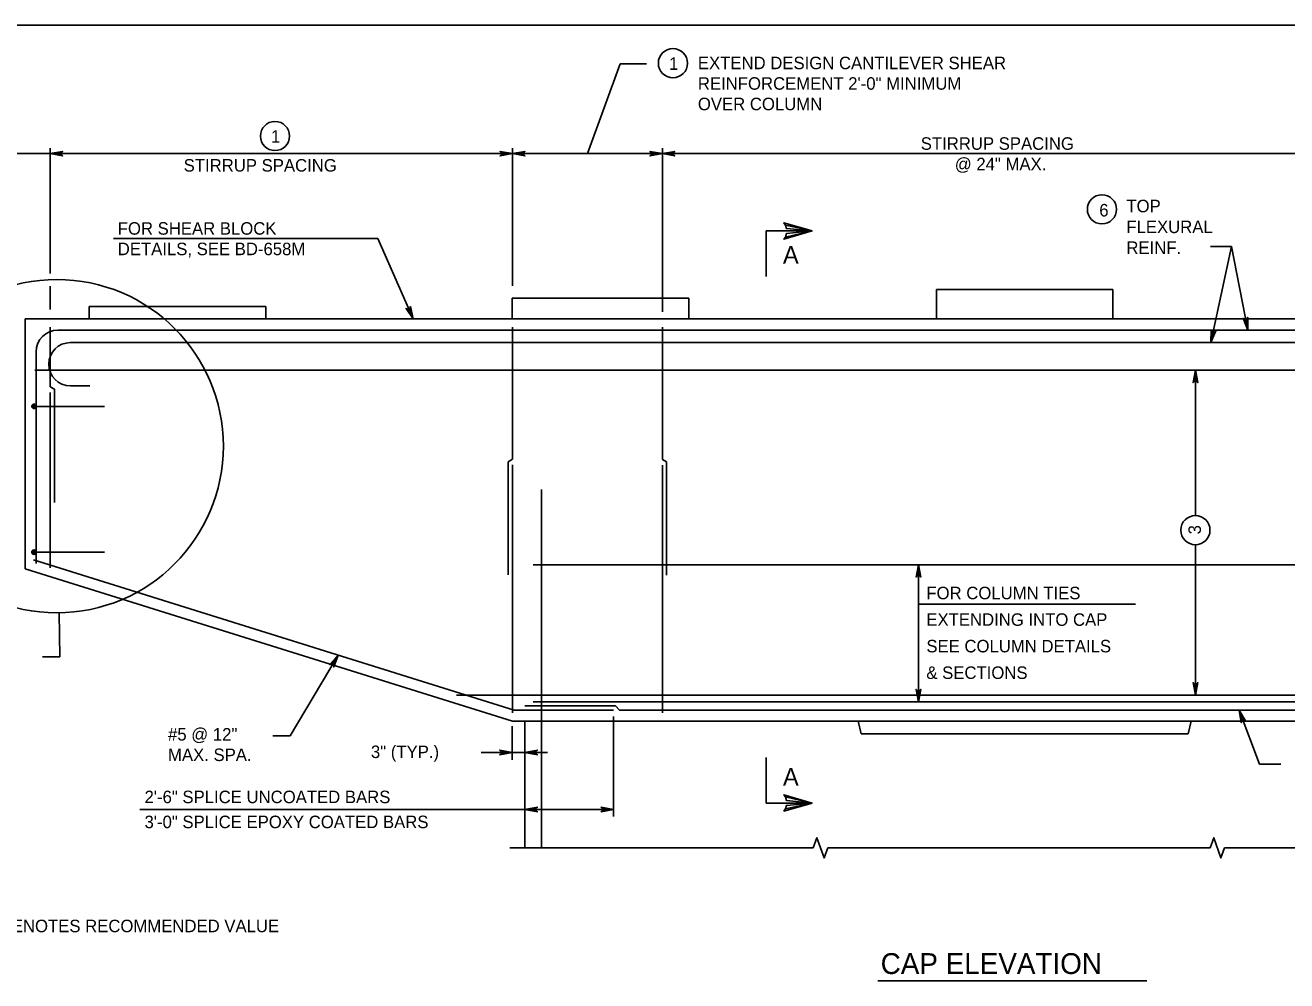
# Model space of a CAD drawing. Extents: x 646165 to 651486, y 296916 to 299292.
# Drawn here: x 649267.7 to 649570.7, y 298453.9 to 298683.3 of the extents above; entities that cross this region are included whole.
import ezdxf

# ---------------------------------------------------------------- set-up
doc = ezdxf.new("R2010")
doc.units = 0
for name, color, linetype in [('1', 7, 'Continuous'), ('2', 7, 'Continuous'), ('51', 7, 'Continuous'), ('52', 7, 'Continuous'), ('53', 7, 'Continuous'), ('54', 7, 'Continuous')]:
    doc.layers.add(name, color=color, linetype=linetype)

msp = doc.modelspace()

# ---------------------------------------------------------------- linework, layer by layer
at = {"layer": '1'}
for p, q in [((649445.63, 298633.87), (649445.63, 298622.94)), ((649456.7, 298633.87), (649445.63, 298633.87)), ((649445.63, 298496.53), (649445.63, 298507.45)), ((649456.7, 298496.53), (649445.63, 298496.53))]:
    msp.add_line(p, q, dxfattribs=at)
for points in [[(649450.28, 298632.4), (649450.52, 298633.24), (649456.7, 298633.87), (649450.28, 298632.4), (649449.95, 298631.88), (649456.7, 298633.87), (649450.52, 298634.43), (649450.3, 298635.26), (649456.7, 298633.87), (649449.95, 298635.82), (649450.3, 298635.26)], [(649450.28, 298498), (649450.52, 298497.15), (649456.7, 298496.53), (649450.28, 298498), (649449.95, 298498.52), (649456.7, 298496.53), (649450.52, 298495.97), (649450.3, 298495.14), (649456.7, 298496.53), (649449.95, 298494.58), (649450.3, 298495.14)]]:
    msp.add_lwpolyline(points, dxfattribs=at)
at = {"layer": '2'}
msp.add_line((648988.59, 298683.25), (649774.59, 298683.25), dxfattribs=at)
at = {"layer": '51'}
for p, q in [((649384.7, 298617.77), (649384.7, 298612.75)), ((649384.7, 298617.77), (649427.1, 298617.77)), ((649427.1, 298617.77), (649427.1, 298612.75)), ((649486.54, 298619.81), (649486.54, 298612.75)), ((649486.54, 298619.81), (649528.94, 298619.81)), ((649528.94, 298619.81), (649528.94, 298612.75)), ((649283.1, 298615.75), (649283.1, 298612.75)), ((649283.1, 298615.75), (649325.5, 298615.75)), ((649325.5, 298615.75), (649325.5, 298612.75)), ((649267.74, 298612.75), (649747.74, 298612.75)), ((649267.74, 298612.75), (649267.74, 298552.75)), ((649384.74, 298516.15), (649267.74, 298552.75)), ((649384.74, 298516.15), (649630.74, 298516.15)), ((649387.74, 298516.15), (649387.74, 298485.78)), ((649467.74, 298516.15), (649468.51, 298513.15)), ((649547.74, 298516.15), (649546.97, 298513.15)), ((649468.51, 298513.15), (649546.97, 298513.15))]:
    msp.add_line(p, q, dxfattribs=at)
at = {"layer": '52'}
for p, q in [((649402.74, 298652.42), (649410.58, 298673.95)), ((649416.91, 298673.95), (649410.58, 298673.95)), ((649273.74, 298653.75), (649273.74, 298623.63)), ((649384.74, 298653.75), (649384.74, 298620.72)), ((649420.74, 298653.75), (649420.74, 298614.41)), ((649261.37, 298652.42), (649384.74, 298652.42)), ((649384.74, 298652.42), (649630.74, 298652.42)), ((649288.97, 298632.05), (649352.43, 298632.05)), ((649360.92, 298612.75), (649352.43, 298632.05)), ((649557.45, 298630.13), (649552.34, 298630.13)), ((649557.45, 298630.13), (649552.45, 298607.07)), ((649557.45, 298630.13), (649561.33, 298610.07)), ((649273.74, 298620.65), (649273.74, 298614.98)), ((649548.74, 298600.45), (649548.74, 298565.54)), ((649548.74, 298558.54), (649548.74, 298522.45)), ((649482.24, 298553.74), (649482.24, 298520.83)), ((649275.92, 298542.21), (649276.09, 298531.64)), ((649482.24, 298544.24), (649534.34, 298544.24)), ((649271.89, 298531.64), (649276.09, 298531.64)), ((649342.87, 298532.05), (649331.36, 298512.67)), ((649409.02, 298517.29), (649409.02, 298493.26)), ((649559.22, 298518.83), (649564.12, 298505.83)), ((649384.69, 298514.99), (649384.69, 298506.93)), ((649327.16, 298512.67), (649331.36, 298512.67)), ((649377.22, 298508.68), (649393.15, 298508.68)), ((649569.23, 298505.83), (649564.12, 298505.83)), ((649295.29, 298494.98), (649409.02, 298494.98)), ((649384.1, 298485.78), (649456.96, 298485.78)), ((649460.46, 298485.78), (649552.25, 298485.78)), ((649555.75, 298485.78), (649631.35, 298485.78))]:
    msp.add_line(p, q, dxfattribs=at)
for points in [[(649273.74, 298652.42), (649276.72, 298652.98), (649276.61, 298652.9), (649276.49, 298652.82), (649276.43, 298652.72), (649276.38, 298652.62), (649276.36, 298652.52), (649276.34, 298652.42), (649276.36, 298652.32), (649276.38, 298652.22), (649276.43, 298652.12), (649276.49, 298652.02), (649276.61, 298651.95), (649276.72, 298651.87), (649273.74, 298652.42), (649276.61, 298651.95), (649276.49, 298652.02), (649273.74, 298652.42), (649276.43, 298652.12), (649276.38, 298652.22), (649273.74, 298652.42), (649276.36, 298652.32), (649276.34, 298652.42), (649273.74, 298652.42), (649276.36, 298652.52), (649276.38, 298652.62), (649273.74, 298652.42), (649276.43, 298652.72), (649276.49, 298652.82), (649273.74, 298652.42), (649276.61, 298652.9)], [(649384.74, 298652.42), (649381.76, 298651.87), (649381.87, 298651.95), (649381.99, 298652.02), (649382.05, 298652.12), (649382.11, 298652.22), (649382.12, 298652.32), (649382.14, 298652.42), (649382.12, 298652.52), (649382.11, 298652.62), (649382.05, 298652.72), (649381.99, 298652.82), (649381.87, 298652.9), (649381.76, 298652.98), (649384.74, 298652.42), (649381.87, 298652.9), (649381.99, 298652.82), (649384.74, 298652.42), (649382.05, 298652.72), (649382.11, 298652.62), (649384.74, 298652.42), (649382.12, 298652.52), (649382.14, 298652.42), (649384.74, 298652.42), (649382.12, 298652.32), (649382.11, 298652.22), (649384.74, 298652.42), (649382.05, 298652.12), (649381.99, 298652.02), (649384.74, 298652.42), (649381.87, 298651.95)], [(649384.74, 298652.42), (649387.72, 298651.87), (649387.61, 298651.95), (649387.49, 298652.02), (649387.43, 298652.12), (649387.38, 298652.22), (649387.36, 298652.32), (649387.34, 298652.42), (649387.36, 298652.52), (649387.38, 298652.62), (649387.43, 298652.72), (649387.49, 298652.82), (649387.61, 298652.9), (649387.72, 298652.98), (649384.74, 298652.42), (649387.61, 298652.9), (649387.49, 298652.82), (649384.74, 298652.42), (649387.43, 298652.72), (649387.38, 298652.62), (649384.74, 298652.42), (649387.36, 298652.52), (649387.34, 298652.42), (649384.74, 298652.42), (649387.36, 298652.32), (649387.38, 298652.22), (649384.74, 298652.42), (649387.43, 298652.12), (649387.49, 298652.02), (649384.74, 298652.42), (649387.61, 298651.95)], [(649420.74, 298652.42), (649417.76, 298651.87), (649417.87, 298651.95), (649417.99, 298652.02), (649418.05, 298652.12), (649418.11, 298652.22), (649418.12, 298652.32), (649418.14, 298652.42), (649418.12, 298652.52), (649418.11, 298652.62), (649418.05, 298652.72), (649417.99, 298652.82), (649417.87, 298652.9), (649417.76, 298652.98), (649420.74, 298652.42), (649417.87, 298652.9), (649417.99, 298652.82), (649420.74, 298652.42), (649418.05, 298652.72), (649418.11, 298652.62), (649420.74, 298652.42), (649418.12, 298652.52), (649418.14, 298652.42), (649420.74, 298652.42), (649418.12, 298652.32), (649418.11, 298652.22), (649420.74, 298652.42), (649418.05, 298652.12), (649417.99, 298652.02), (649420.74, 298652.42), (649417.87, 298651.95)], [(649420.74, 298652.42), (649423.72, 298651.87), (649423.61, 298651.95), (649423.49, 298652.02), (649423.43, 298652.12), (649423.38, 298652.22), (649423.36, 298652.32), (649423.34, 298652.42), (649423.36, 298652.52), (649423.38, 298652.62), (649423.43, 298652.72), (649423.49, 298652.82), (649423.61, 298652.9), (649423.72, 298652.98), (649420.74, 298652.42), (649423.61, 298652.9), (649423.49, 298652.82), (649420.74, 298652.42), (649423.43, 298652.72), (649423.38, 298652.62), (649420.74, 298652.42), (649423.36, 298652.52), (649423.34, 298652.42), (649420.74, 298652.42), (649423.36, 298652.32), (649423.38, 298652.22), (649420.74, 298652.42), (649423.43, 298652.12), (649423.49, 298652.02), (649420.74, 298652.42), (649423.61, 298651.95)], [(649360.92, 298612.75), (649359.2, 298615.25), (649359.32, 298615.18), (649359.44, 298615.1), (649359.56, 298615.09), (649359.67, 298615.08), (649359.77, 298615.1), (649359.87, 298615.13), (649359.95, 298615.18), (649360.04, 298615.24), (649360.11, 298615.33), (649360.17, 298615.43), (649360.2, 298615.56), (649360.23, 298615.7), (649360.92, 298612.75), (649360.2, 298615.56), (649360.17, 298615.43), (649360.92, 298612.75), (649360.11, 298615.33), (649360.04, 298615.24), (649360.92, 298612.75), (649359.95, 298615.18), (649359.87, 298615.13), (649360.92, 298612.75), (649359.77, 298615.1), (649359.67, 298615.08), (649360.92, 298612.75), (649359.56, 298615.09), (649359.44, 298615.1), (649360.92, 298612.75), (649359.32, 298615.18)], [(649561.33, 298610.07), (649560.21, 298612.89), (649560.31, 298612.79), (649560.41, 298612.69), (649560.52, 298612.65), (649560.63, 298612.61), (649560.73, 298612.62), (649560.83, 298612.62), (649560.93, 298612.65), (649561.02, 298612.69), (649561.11, 298612.77), (649561.2, 298612.84), (649561.25, 298612.97), (649561.31, 298613.1), (649561.33, 298610.07), (649561.25, 298612.97), (649561.2, 298612.84), (649561.33, 298610.07), (649561.11, 298612.77), (649561.02, 298612.69), (649561.33, 298610.07), (649560.93, 298612.65), (649560.83, 298612.62), (649561.33, 298610.07), (649560.73, 298612.62), (649560.63, 298612.61), (649561.33, 298610.07), (649560.52, 298612.65), (649560.41, 298612.69), (649561.33, 298610.07), (649560.31, 298612.79)], [(649552.45, 298607.07), (649552.54, 298610.1), (649552.59, 298609.97), (649552.65, 298609.84), (649552.73, 298609.76), (649552.82, 298609.68), (649552.91, 298609.64), (649553, 298609.61), (649553.11, 298609.6), (649553.21, 298609.6), (649553.32, 298609.63), (649553.43, 298609.67), (649553.53, 298609.77), (649553.63, 298609.86), (649552.45, 298607.07), (649553.53, 298609.77), (649553.43, 298609.67), (649552.45, 298607.07), (649553.32, 298609.63), (649553.21, 298609.6), (649552.45, 298607.07), (649553.11, 298609.6), (649553, 298609.61), (649552.45, 298607.07), (649552.91, 298609.64), (649552.82, 298609.68), (649552.45, 298607.07), (649552.73, 298609.76), (649552.65, 298609.84), (649552.45, 298607.07), (649552.59, 298609.97)], [(649548.74, 298600.45), (649549.3, 298597.46), (649549.22, 298597.58), (649549.14, 298597.69), (649549.04, 298597.75), (649548.94, 298597.81), (649548.84, 298597.83), (649548.74, 298597.85), (649548.64, 298597.83), (649548.54, 298597.81), (649548.44, 298597.75), (649548.34, 298597.69), (649548.26, 298597.58), (649548.18, 298597.46), (649548.74, 298600.45), (649548.26, 298597.58), (649548.34, 298597.69), (649548.74, 298600.45), (649548.44, 298597.75), (649548.54, 298597.81), (649548.74, 298600.45), (649548.64, 298597.83), (649548.74, 298597.85), (649548.74, 298600.45), (649548.84, 298597.83), (649548.94, 298597.81), (649548.74, 298600.45), (649549.04, 298597.75), (649549.14, 298597.69), (649548.74, 298600.45), (649549.22, 298597.58)], [(649482.24, 298553.74), (649482.8, 298550.76), (649482.72, 298550.87), (649482.64, 298550.99), (649482.54, 298551.05), (649482.44, 298551.11), (649482.34, 298551.12), (649482.24, 298551.14), (649482.14, 298551.12), (649482.04, 298551.11), (649481.94, 298551.05), (649481.84, 298550.99), (649481.76, 298550.87), (649481.68, 298550.76), (649482.24, 298553.74), (649481.76, 298550.87), (649481.84, 298550.99), (649482.24, 298553.74), (649481.94, 298551.05), (649482.04, 298551.11), (649482.24, 298553.74), (649482.14, 298551.12), (649482.24, 298551.14), (649482.24, 298553.74), (649482.34, 298551.12), (649482.44, 298551.11), (649482.24, 298553.74), (649482.54, 298551.05), (649482.64, 298550.99), (649482.24, 298553.74), (649482.72, 298550.87)], [(649342.87, 298532.05), (649341.83, 298529.2), (649341.82, 298529.34), (649341.81, 298529.48), (649341.75, 298529.58), (649341.69, 298529.69), (649341.62, 298529.75), (649341.54, 298529.82), (649341.44, 298529.85), (649341.35, 298529.89), (649341.23, 298529.89), (649341.12, 298529.89), (649340.99, 298529.83), (649340.86, 298529.77), (649342.87, 298532.05), (649340.99, 298529.83), (649341.12, 298529.89), (649342.87, 298532.05), (649341.23, 298529.89), (649341.35, 298529.89), (649342.87, 298532.05), (649341.44, 298529.85), (649341.54, 298529.82), (649342.87, 298532.05), (649341.62, 298529.75), (649341.69, 298529.69), (649342.87, 298532.05), (649341.75, 298529.58), (649341.81, 298529.48), (649342.87, 298532.05), (649341.82, 298529.34)], [(649482.24, 298520.83), (649481.68, 298523.81), (649481.76, 298523.69), (649481.84, 298523.58), (649481.94, 298523.52), (649482.04, 298523.46), (649482.14, 298523.44), (649482.24, 298523.43), (649482.34, 298523.44), (649482.44, 298523.46), (649482.54, 298523.52), (649482.64, 298523.58), (649482.72, 298523.69), (649482.8, 298523.81), (649482.24, 298520.83), (649482.72, 298523.69), (649482.64, 298523.58), (649482.24, 298520.83), (649482.54, 298523.52), (649482.44, 298523.46), (649482.24, 298520.83), (649482.34, 298523.44), (649482.24, 298523.43), (649482.24, 298520.83), (649482.14, 298523.44), (649482.04, 298523.46), (649482.24, 298520.83), (649481.94, 298523.52), (649481.84, 298523.58), (649482.24, 298520.83), (649481.76, 298523.69)], [(649548.74, 298522.45), (649548.18, 298525.43), (649548.26, 298525.31), (649548.34, 298525.2), (649548.44, 298525.14), (649548.54, 298525.08), (649548.64, 298525.06), (649548.74, 298525.05), (649548.84, 298525.06), (649548.94, 298525.08), (649549.04, 298525.14), (649549.14, 298525.2), (649549.22, 298525.31), (649549.3, 298525.43), (649548.74, 298522.45), (649549.22, 298525.31), (649549.14, 298525.2), (649548.74, 298522.45), (649549.04, 298525.14), (649548.94, 298525.08), (649548.74, 298522.45), (649548.84, 298525.06), (649548.74, 298525.05), (649548.74, 298522.45), (649548.64, 298525.06), (649548.54, 298525.08), (649548.74, 298522.45), (649548.44, 298525.14), (649548.34, 298525.2), (649548.74, 298522.45), (649548.26, 298525.31)], [(649559.22, 298518.83), (649560.79, 298516.23), (649560.68, 298516.31), (649560.56, 298516.39), (649560.45, 298516.41), (649560.34, 298516.43), (649560.24, 298516.41), (649560.14, 298516.39), (649560.05, 298516.34), (649559.96, 298516.29), (649559.89, 298516.2), (649559.82, 298516.11), (649559.78, 298515.97), (649559.75, 298515.84), (649559.22, 298518.83), (649559.78, 298515.97), (649559.82, 298516.11), (649559.22, 298518.83), (649559.89, 298516.2), (649559.96, 298516.29), (649559.22, 298518.83), (649560.05, 298516.34), (649560.14, 298516.39), (649559.22, 298518.83), (649560.24, 298516.41), (649560.34, 298516.43), (649559.22, 298518.83), (649560.45, 298516.41), (649560.56, 298516.39), (649559.22, 298518.83), (649560.68, 298516.31)], [(649384.69, 298508.68), (649381.71, 298509.24), (649381.83, 298509.16), (649381.94, 298509.08), (649382, 298508.98), (649382.06, 298508.88), (649382.08, 298508.78), (649382.09, 298508.68), (649382.08, 298508.58), (649382.06, 298508.48), (649382, 298508.38), (649381.94, 298508.28), (649381.83, 298508.2), (649381.71, 298508.12), (649384.69, 298508.68), (649381.83, 298508.2), (649381.94, 298508.28), (649384.69, 298508.68), (649382, 298508.38), (649382.06, 298508.48), (649384.69, 298508.68), (649382.08, 298508.58), (649382.09, 298508.68), (649384.69, 298508.68), (649382.08, 298508.78), (649382.06, 298508.88), (649384.69, 298508.68), (649382, 298508.98), (649381.94, 298509.08), (649384.69, 298508.68), (649381.83, 298509.16)], [(649387.74, 298508.68), (649390.72, 298508.12), (649390.61, 298508.2), (649390.49, 298508.28), (649390.43, 298508.38), (649390.38, 298508.48), (649390.36, 298508.58), (649390.34, 298508.68), (649390.36, 298508.78), (649390.38, 298508.88), (649390.43, 298508.98), (649390.49, 298509.08), (649390.61, 298509.16), (649390.72, 298509.24), (649387.74, 298508.68), (649390.61, 298509.16), (649390.49, 298509.08), (649387.74, 298508.68), (649390.43, 298508.98), (649390.38, 298508.88), (649387.74, 298508.68), (649390.36, 298508.78), (649390.34, 298508.68), (649387.74, 298508.68), (649390.36, 298508.58), (649390.38, 298508.48), (649387.74, 298508.68), (649390.43, 298508.38), (649390.49, 298508.28), (649387.74, 298508.68), (649390.61, 298508.2)], [(649387.74, 298494.98), (649390.72, 298495.53), (649390.61, 298495.46), (649390.49, 298495.38), (649390.43, 298495.28), (649390.38, 298495.18), (649390.36, 298495.08), (649390.34, 298494.98), (649390.36, 298494.88), (649390.38, 298494.78), (649390.43, 298494.68), (649390.49, 298494.58), (649390.61, 298494.5), (649390.72, 298494.42), (649387.74, 298494.98), (649390.61, 298494.5), (649390.49, 298494.58), (649387.74, 298494.98), (649390.43, 298494.68), (649390.38, 298494.78), (649387.74, 298494.98), (649390.36, 298494.88), (649390.34, 298494.98), (649387.74, 298494.98), (649390.36, 298495.08), (649390.38, 298495.18), (649387.74, 298494.98), (649390.43, 298495.28), (649390.49, 298495.38), (649387.74, 298494.98), (649390.61, 298495.46)], [(649409.02, 298494.98), (649406.04, 298494.42), (649406.15, 298494.5), (649406.27, 298494.58), (649406.33, 298494.68), (649406.39, 298494.78), (649406.4, 298494.88), (649406.42, 298494.98), (649406.4, 298495.08), (649406.39, 298495.18), (649406.33, 298495.28), (649406.27, 298495.38), (649406.15, 298495.46), (649406.04, 298495.53), (649409.02, 298494.98), (649406.15, 298495.46), (649406.27, 298495.38), (649409.02, 298494.98), (649406.33, 298495.28), (649406.39, 298495.18), (649409.02, 298494.98), (649406.4, 298495.08), (649406.42, 298494.98), (649409.02, 298494.98), (649406.4, 298494.88), (649406.39, 298494.78), (649409.02, 298494.98), (649406.33, 298494.68), (649406.27, 298494.58), (649409.02, 298494.98), (649406.15, 298494.5)], [(649460.46, 298485.78), (649459.59, 298483.37), (649457.84, 298488.18), (649456.96, 298485.78)], [(649555.75, 298485.78), (649554.88, 298483.37), (649553.13, 298488.18), (649552.25, 298485.78)]]:
    msp.add_lwpolyline(points, dxfattribs=at)
for centre, radius in [((649423.28, 298674.14), 3.5), ((649327.72, 298656.65), 3.5), ((649526.3, 298639.06), 3.5), ((649275.32, 298582.2), 40), ((649548.74, 298562.04), 3.5)]:
    msp.add_circle(centre, radius, dxfattribs=at)
at = {"layer": '53'}
msp.add_line((649472.51, 298453.86), (649537.07, 298453.86), dxfattribs=at)
at = {"layer": '54'}
for p, q in [((649273.74, 298610.75), (649273.74, 298596.43)), ((649275.58, 298610.07), (649739.9, 298610.07)), ((649384.74, 298610.75), (649384.74, 298579.05)), ((649420.74, 298610.75), (649420.74, 298579.02)), ((649278.58, 298607.07), (649736.9, 298607.07)), ((649270.38, 298604.87), (649270.38, 298554.02)), ((649270.06, 298600.45), (649745.42, 298600.45)), ((649274.74, 298595.85), (649273.74, 298596.43)), ((649278.58, 298596.67), (649283.22, 298596.67)), ((649273.74, 298595.05), (649273.74, 298552.96)), ((649274.74, 298595.85), (649274.74, 298568.65)), ((649269.84, 298591.76), (649286.81, 298591.76)), ((649383.74, 298578.48), (649384.74, 298579.05)), ((649383.74, 298578.48), (649383.74, 298551.28)), ((649421.74, 298578.45), (649420.74, 298579.02)), ((649421.74, 298578.45), (649421.74, 298551.25)), ((649384.74, 298577.68), (649384.74, 298518.21)), ((649420.74, 298577.65), (649420.74, 298518.15)), ((649391.74, 298571.78), (649391.74, 298485.78)), ((649269.84, 298556.75), (649286.81, 298556.75)), ((649385.15, 298518.83), (649269.74, 298554.93)), ((649389.74, 298553.74), (649625.74, 298553.74)), ((649371.3, 298522.45), (649644.18, 298522.45)), ((649389.74, 298520.83), (649625.74, 298520.83)), ((649385.15, 298518.83), (649409.02, 298518.83)), ((649409.46, 298519.83), (649387.74, 298519.83)), ((649409.46, 298519.83), (649410.46, 298518.83)), ((649410.46, 298518.83), (649605.02, 298518.83))]:
    msp.add_line(p, q, dxfattribs=at)
for centre, radius in [((649269.84, 298591.76), 0.533), ((649269.84, 298591.76), 0.4), ((649269.84, 298591.76), 0.267), ((649269.84, 298591.76), 0.133), ((649269.84, 298556.75), 0.533), ((649269.84, 298556.75), 0.4), ((649269.84, 298556.75), 0.267), ((649269.84, 298556.75), 0.133)]:
    msp.add_circle(centre, radius, dxfattribs=at)
for centre, end in [((649275.58, 298604.87), 180), ((649278.58, 298601.87), 270)]:
    msp.add_arc(centre, 5.2, 90, end, dxfattribs=at)

# ---------------------------------------------------------------- texts
at = {"layer": '1'}
for p in [(649449.7, 298626.03), (649449.7, 298500.71)]:
    msp.add_text('A', height=4.23, dxfattribs=at).set_placement(p)
at = {"layer": '53'}
for s, height, p in [('1', 3, (649422.33, 298672.54)), ('EXTEND DESIGN CANTILEVER SHEAR', 3, (649429.27, 298672.7)), ('REINFORCEMENT 2\'-0" MINIMUM', 3, (649429.27, 298667.77)), ('OVER COLUMN', 3, (649429.27, 298662.85)), ('1', 3, (649326.76, 298655.05)), ('STIRRUP SPACING', 3, (649482.79, 298653.35)), ('STIRRUP SPACING', 3, (649305.79, 298648.12)), ('@ 24" MAX.', 3, (649490.96, 298648.43)), ('TOP', 3, (649532.17, 298638.35)), ('6', 3, (649525.66, 298637.35)), ('FOR SHEAR BLOCK', 3, (649289.96, 298632.97)), ('FLEXURAL', 3, (649532.17, 298633.35)), ('DETAILS, SEE BD-658M', 3, (649289.96, 298628.05)), ('REINF.', 3, (649532.17, 298628.35)), ('FOR COLUMN TIES', 3, (649484.14, 298545.45)), ('EXTENDING INTO CAP', 3, (649484.14, 298539.07)), ('SEE COLUMN DETAILS', 3, (649484.14, 298532.7)), ('& SECTIONS', 3, (649484.14, 298526.32)), ('#5 @ 12"', 3, (649302.03, 298511.53)), ('MAX. SPA.', 3, (649302.03, 298506.61)), ('3" (TYP.)', 3, (649350.76, 298507.33)), ('2\'-6" SPLICE UNCOATED BARS', 3, (649296.39, 298496.5)), ('3\'-0" SPLICE EPOXY COATED BARS', 3, (649296.39, 298490.5)), ('- DENOTES RECOMMENDED VALUE', 3, (649259.17, 298465.52)), ('CAP ELEVATION', 5, (649473.17, 298455.49))]:
    msp.add_text(s, height=height, dxfattribs=at).set_placement(p)
msp.add_text('3', height=3, rotation=90, dxfattribs=at).set_placement((649550.06, 298561.02))

doc.saveas('drawing.dxf')
